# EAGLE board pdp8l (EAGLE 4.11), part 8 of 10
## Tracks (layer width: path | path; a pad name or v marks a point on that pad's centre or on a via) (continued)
N$184  (via drill 0.61) (continued)
  Route2 0.203: v4.88,181.1 4.88,182.32 6.1,183.54 6.1,195.33 8.13,197.36 8.13,198.17 37.8,227.84 37.8,231.9 45.52,239.62 47.55,239.62 48.77,240.84 A33.M1
  Route15 0.203: v20.32,131.52 16.26,135.59 16.26,137.62 15.44,138.43 15.44,144.53 14.22,145.75 14.22,147.37 13.01,148.59 13.01,160.38 9.35,164.03 9.35,168.91 8.94,169.32 8.94,170.94 8.13,171.75 8.13,172.57 6.5,174.19 6.5,179.48 v4.88,181.1
N$185  (via drill 0.61)
  Top 0.203: v24.79,150.22 24.79,144.93 25.2,144.53 25.2,125.83 23.98,124.61 C35.E1 | 47.95,189.23 v47.95,173.38 | 47.95,189.23 48.77,190.04 B33.E1 | v47.95,214.83 47.95,189.23
  Route2 0.203: v47.95,173.38 v24.79,150.22
  Route15 0.203: v47.95,214.83 34.54,228.24 34.54,238.81 33.33,240.03 33.33,243.69 A34.L1
N$186  (via drill 0.61)
  Top 0.203: v35.36,118.52 35.36,82.35 28.85,75.84 28.85,36.83 30.07,35.61 D34.M2
  Route2 0.203: v4.06,182.32 3.25,183.13 3.25,193.29 6.1,196.14 6.1,203.05 12.19,209.14 12.19,217.68 12.6,218.08 12.6,220.12 16.66,224.18 17.48,224.18 39.01,245.72 40.64,245.72 42.27,247.34 A33.K2
  Route15 0.203: v54.86,128.68 47.95,135.59 47.95,137.21 47.55,137.62 47.55,139.24 13.01,173.79 13.01,177.85 5.28,185.57 4.06,185.57 2.44,183.95 v4.06,182.32
  Bottom 0.203: v35.36,118.52 36.58,119.74 38.61,119.74 39.01,119.33 41.86,119.33 50.8,128.27 54.46,128.27 v54.86,128.68
N$187  (via drill 0.61)
  Top 0.203: v22.35,155.09 22.35,119.33 23.57,118.11 C35.H1 | v38.2,238.81 38.2,216.46 37.8,216.05 37.8,206.7 v37.39,206.3 | v46.74,205.89 47.55,205.08 47.55,186.38 v47.14,185.98
  Route2 0.203: v22.35,155.09 22.76,155.09 34.54,166.88 34.54,167.69 43.48,176.63 43.89,176.63 44.3,177.04 44.3,181.1 45.52,182.32 47.55,182.32 48.77,183.54 B33.H1
  Bottom 0.203: v38.2,238.81 34.54,238.81 34.14,238.4 A34.N1 | v37.39,206.3 37.8,205.89 v46.74,205.89 | v47.14,185.98 48.36,184.76 48.77,184.76 B33.H1
N$188  (via drill 0.61)
  Top 0.203: v36.98,122.17 37.8,122.99 37.8,137.21 37.39,137.62 37.39,151.44 37.8,151.84 37.8,168.91 v37.39,169.32 | v45.92,177.85 45.92,180.29 B33.J1 | v35.76,230.68 35.36,230.28 35.36,194.92 v36.98,193.29
  Route2 0.203: v45.92,177.85 v37.39,169.32 | v35.76,230.68 35.36,230.28 34.14,231.5 A34.R1
  Route15 0.203: v36.98,193.29 36.98,192.07 44.3,184.76 44.3,182.73 45.52,181.51 B33.J1
  Bottom 0.203: v36.98,122.17 30.89,116.08 22.35,116.08 21.13,114.86 C35.J1
N$189  (via drill 0.61)
  Top 0.203: v45.11,136.4 46.33,137.62 46.33,147.37 47.95,149 47.95,159.56 47.14,160.38 47.14,161.19 47.55,161.59 47.55,171.75 | 47.55,171.75 47.55,172.57 46.74,173.38 46.74,174.19 B33.L1 | v48.77,220.12 50.39,218.49 50.39,174.6 47.55,171.75
  Route2 0.203: v45.11,136.4 29.26,120.55 29.26,118.92 20.73,110.39 20.73,108.76 C35.L1
  Bottom 0.203: v48.77,220.12 48.36,220.52 35.36,220.52 34.14,219.3 A34.V1
N$190  (via drill 0.61)
  Top 0.203: v47.95,160.78 47.95,170.13 48.77,170.94 B33.M1 | v26.42,203.45 26.42,214.83 28.45,216.86 28.45,219.71 28.04,220.12 28.04,220.93 28.45,221.34 28.45,241.66 29.67,242.88 29.67,245.31 28.85,246.13 28.85,258.32 30.07,259.54 A34.E2
  Route2 0.203: v15.44,125.83 15.44,126.24 18.69,129.49 18.69,133.55 23.16,138.02 24.79,138.02 31.7,144.93 32.11,144.93 v47.95,160.78
  Route15 0.203: v15.44,125.83 16.26,125.02 16.26,122.99 22.35,116.89 22.35,110.39 23.57,109.17 23.57,105.51 C35.M1 | v26.42,203.45 23.57,200.61 27.23,196.95 27.23,196.14 28.85,194.51 28.85,189.64 45.11,173.38 46.74,173.38 48.77,171.35 B33.M1
N$191  (via drill 0.61)
  Top 0.203: v16.66,96.98 16.26,97.38 v16.26,121.77 | v49.17,160.78 49.17,164.44 B33.P1 | v24.79,255.47 21.95,255.47 21.95,218.49 21.13,217.68 v21.13,202.23
  Route2 0.203: v16.26,121.77 16.26,126.24 21.13,131.12 21.13,131.93 28.45,139.24 28.45,140.06 v49.17,160.78
  Route15 0.203: v24.79,255.47 25.6,254.66 29.67,254.66 A34.H2 | v21.13,202.23 26.82,196.54 26.82,195.73 28.45,194.11 28.45,188.82 39.01,178.26 39.01,177.44 47.55,168.91 47.55,166.88 48.77,165.66 B33.P1
  Bottom 0.203: v16.66,96.98 21.95,96.98 23.16,98.2 C35.P1
N$192  (via drill 0.61)
  Route2 0.203: C35.S1 23.16,91.69 19.1,91.69 18.29,90.88 9.75,90.88 1.22,99.42 2.85,101.04 2.85,105.92 8.53,111.61 8.53,112.83 18.69,122.99 18.69,127.86 32.92,142.09 34.54,142.09 47.55,155.09 47.55,156.31 49.17,157.94 B33.S1 | v14.22,228.24 30.07,244.09 30.07,246.94 A34.K2
  Route15 0.203: v14.22,228.24 14.22,227.43 15.44,226.21 15.44,201.02 25.2,191.26 25.2,187.2 32.92,179.48 32.92,178.26 49.99,161.19 49.99,158.75 B33.S1
N$193  (via drill 0.61)
  Top 0.203: v15.04,146.15 15.44,145.75 15.44,128.27 14.63,127.46 C35.D2 | 35.36,181.1 v35.36,166.88 | 35.36,181.1 38.2,183.95 38.2,191.67 39.42,192.89 B33.D2 | 35.36,181.1 35.36,189.23 34.95,189.64 34.95,245.72 32.92,245.72 32.11,244.91 32.11,243.69 30.48,242.06 A34.M2
  Route2 0.203: v15.04,146.15 15.04,146.56 v35.36,166.88
N$194  (via drill 0.61)
  Top 0.203: v20.73,144.12 19.1,142.49 19.1,126.24 17.48,124.61 C35.E2 | v44.7,145.75 44.7,188.82 43.48,190.04 B33.E2 | v31.29,191.67 31.29,233.53 30.48,234.34 A34.P2
  Bottom 0.203: v20.73,144.12 22.76,146.15 44.3,146.15 v44.7,145.75 | v31.29,191.67 39.01,191.67 39.83,190.86 42.27,190.86 B33.E2
N$195  (via drill 0.61)
  Top 0.203: v44.7,125.83 44.3,126.24 44.3,144.93 43.89,145.34 43.89,151.44 44.3,151.84 44.3,182.32 43.08,183.54 B33.H2 | v32.11,228.24 31.7,227.84 31.7,192.48 33.33,190.86 v33.33,189.23
  Route2 0.203: v32.11,228.24 30.89,228.24 A34.S2
  Bottom 0.203: v44.7,125.83 36.58,125.83 30.07,119.33 19.1,119.33 17.88,118.11 C35.H2 | v33.33,189.23 33.73,188.82 40.23,188.82 42.67,186.38 42.67,184.76 B33.H2
N$196  (via drill 0.61)
  Top 0.203: v38.2,177.85 v38.2,138.02 | v32.11,179.07 32.11,181.91 34.54,184.35 34.54,188.01 34.14,188.42 34.14,190.86 32.11,192.89 32.11,226.21 32.92,227.03 32.92,229.06 31.7,230.28 31.7,236.37 29.67,236.37 28.85,235.56 28.85,224.18 30.07,222.96 A34.U2
  Route2 0.203: v38.2,138.02 35.76,138.02 21.95,124.21 21.95,120.14 19.91,118.11 19.91,115.67 17.88,113.64 17.88,111.61 C35.K2
  Bottom 0.203: B33.K2 42.27,177.85 v38.2,177.85 38.2,178.26 37.39,179.07 v32.11,179.07
N$197  (via drill 0.61)
  Top 0.203: v230.84,253.44 228.4,251 228.4,240.03 219.46,231.09 219.46,207.52 217.42,205.49 217.42,201.83 216.21,200.61 216.21,199.39 v217.42,198.17 | v224.33,177.85 225.15,177.04 225.15,172.97 224.74,172.57 224.74,169.32 225.55,168.5 225.55,78.69 v232.87,71.37
  Route15 0.203: v217.42,198.17 217.42,195.73 218.64,194.51 218.64,183.54 v224.33,177.85 | v232.87,71.37 242.21,62.03 246.69,62.03 v271.88,36.83
  Bottom 0.203: v230.84,253.44 233.27,255.88 249.94,255.88 252.37,258.32 283.67,258.32 283.67,254.66 A14.H2 | v271.88,36.83 298.7,36.83 299.52,37.64 D13.L1
N$198  (via drill 0.61)
  Top 0.203: v18.29,102.67 18.29,99.42 17.88,99.01 C35.P2 | v35.76,163.63 34.54,162.41 34.54,132.33 32.11,129.9 v32.11,105.92
  Bottom 0.203: v18.29,102.67 18.69,103.07 32.11,103.07 | 32.11,103.07 114.61,103.07 115.42,102.26 C27.N2 | v35.76,163.63 36.98,163.63 37.39,164.03 41.45,164.03 42.27,164.85 B33.P2 | 32.11,103.07 v32.11,105.92
N$199  (via drill 0.61)
  Top 0.203: v29.67,93.73 32.11,96.16 32.11,104.7 34.54,107.14 34.54,131.52 35.36,132.33 35.36,156.72 v35.76,157.12
  Bottom 0.203: v29.67,93.73 19.1,93.73 17.88,92.51 C35.S2 | v35.76,157.12 36.17,157.53 39.01,157.53 39.83,158.34 42.27,158.34 B33.S2
N$200
  Bottom 0.203: C32.J2 52.83,113.64 54.05,112.42 60.55,112.42 61.37,111.61 C32.K1
N$201
  Top 0.203: D17.A1 251.97,66.09 249.94,64.06 249.94,63.65 D17.B1 249.94,63.25 251.97,61.21 251.97,60.81 D17.C1 251.97,60 251.97,59.59 249.94,57.56 D17.D1 249.12,56.34 249.12,51.46 D17.F1 | D17.J1 249.94,44.55 251.97,46.58 251.97,46.99 D17.H1
  Bottom 0.203: D17.J1 249.53,43.74 251.56,41.71 251.97,41.71 D17.K1 | 250.34,49.43 251.56,48.21 251.97,48.21 D17.H1 | 250.34,49.43 249.53,50.24 D17.F1 | 250.34,49.43 260.1,49.43 261.31,50.65 D16.F1
N$202  (via drill 0.61)
  Top 0.203: v85.34,145.75 85.75,146.15 85.75,181.91 86.16,182.32 86.16,185.98 87.38,187.2 87.38,188.42 86.16,189.64 86.16,219.3 v86.56,219.71
  Route2 0.203: v85.34,145.75 76.81,137.21 76.81,135.18 40.64,99.01 36.98,99.01 C34.P1
  Route15 0.203: v86.56,219.71 86.56,220.93 82.91,224.59 82.91,229.46 78.84,233.53 78.03,233.53 69.09,242.47 67.46,242.47 65.84,244.09 AB31.AL2
N$203  (via drill 0.61)
  Top 0.203: v281.23,97.79 279.6,99.42 279.6,130.71 277.98,132.33 277.98,135.99 C15.A1
  Route15 0.203: v281.23,97.79 293.42,85.6 293.42,83.16 C13.V2
N$204  (via drill 0.61)
  Top 0.203: v271.07,64.06 272.69,65.68 272.69,86.41 271.88,87.22 271.88,90.47 272.69,91.29 272.69,109.58 | 272.69,109.58 271.88,110.39 C15.K2 | v270.26,134.37 272.69,131.93 272.69,109.58
  Route2 0.203: v271.07,64.06 258.47,51.46 256.03,51.46 D16.F2
  Bottom 0.203: v270.26,134.37 273.1,134.37 273.91,133.55 C15.B1
N$205  (via drill 0.61)
  Top 0.203: v281.63,111.61 282.45,110.79 282.45,83.97 282.85,83.57 282.85,49.02 283.67,48.21 D14.H2
  Route2 0.203: v281.63,111.61 277.98,115.27 279.2,116.48 279.2,128.27 277.98,129.49 C15.C1
N$206  (via drill 0.61)
  Top 0.203: v273.51,55.93 273.51,45.77 274.32,44.96 D15.J1 | v254.41,97.38 254.41,59.18 255.63,57.96 D16.D2
  Bottom 0.203: v273.51,55.93 272.29,55.93 269.85,58.37 256.85,58.37 256.03,57.56 D16.D2 | v254.41,97.38 254,96.98 247.9,96.98 246.69,98.2 C17.P2
N$207  (via drill 0.61)
  Top 0.203: v263.75,120.14 263.75,94.94 257.25,88.44 257.25,32.36 256.03,32.36 D16.N2
  Bottom 0.203: v263.75,120.14 267.82,120.14 C15.F2
N$208
  Top 0.203: D14.N2 281.63,31.95 285.29,31.95 285.29,35.61 286.11,36.42 286.11,40.49 290.17,44.55 290.17,46.99 D14.H1
N$209
  Top 0.203: D14.M2 284.48,35.61 285.7,36.83 285.7,40.89 289.36,44.55 289.36,52.68 290.17,53.49 D14.E1
N$210  (via drill 0.61)
  Top 0.203: v285.29,49.02 286.92,47.4 286.92,46.18 | 286.92,46.18 286.92,44.96 D14.J1 | 286.92,46.18 282.45,46.18 278.38,50.24 278.38,51.05 279.2,51.87 279.2,54.71 276.35,57.56 276.35,112.42 275.13,113.64 C15.J1 | v269.44,36.83 270.26,37.64 270.26,46.18 271.07,46.99 D15.H2
  Route2 0.203: D17.N1 249.94,31.95 249.94,32.36 251.97,34.39 D17.M1
  Bottom 0.203: v285.29,49.02 272.69,49.02 271.88,48.21 D15.H2 | v269.44,36.83 254.81,36.83 253.19,35.2 D17.M1
N$211
  Route2 0.203: D15.L2 269.04,38.46 270.66,38.46 275.95,43.74 275.95,45.36 277.57,46.99 D15.H1
N$212
  Top 0.203: D15.T2 268.63,19.76 270.26,21.39 270.26,31.55 276.35,37.64 276.35,52.68 277.17,53.49 D15.E1
N$213  (via drill 0.61)
  Top 0.203: v269.04,109.58 269.44,109.17 269.44,86.41 267,83.97 267,22.2 263.35,18.54 263.35,17.73 261.31,17.73 260.5,18.54 260.5,23.42 261.72,24.64 D16.R1
  Bottom 0.203: v269.04,109.58 269.44,109.98 276.35,109.98 277.17,110.79 C15.K1
N$214  (via drill 0.61)
  Top 0.203: v120.29,146.96 120.29,156.72 119.08,157.94 B27.S2 | v178,146.56 178,154.28 178.82,155.09 B22.T2
  Bottom 0.203: v120.29,146.96 131.67,146.96 133.3,145.34 166.62,145.34 167.84,146.56 v178,146.56
N$215  (via drill 0.61)
  Top 0.203: v269.44,52.68 269.85,53.09 269.85,110.79 267,113.64 267,125.02 268.22,126.24 C15.D2
  Bottom 0.203: v269.44,52.68 285.7,52.68 286.92,51.46 D14.F1
N$216  (via drill 0.61)
  Route2 0.203: v153.62,184.76 147.93,179.07 143.46,179.07 127.61,163.22 121.51,163.22 120.29,162 116.64,162 B27.R2
  Route15 0.203: v153.62,184.76 153.62,184.35 179.63,158.34 182.07,158.34 B22.S2
N$217  (via drill 0.61)
  Route2 0.203: v89.41,157.53 89.41,157.94 97.13,165.66 97.13,166.47 114.2,183.54 114.2,185.57 115.42,186.79 B27.F2
  Bottom 0.203: v89.41,157.53 39.83,157.53 38.61,156.31 35.36,156.31 34.95,156.72 19.91,156.72 19.51,156.31 17.88,156.31 17.48,156.72 6.91,156.72 5.28,158.34 B36.S2
N$218  (via drill 0.61)
  Top 0.203: v50.39,146.96 50.8,147.37 50.8,205.08 51.61,205.89 v51.61,213.21 | v106.48,215.65 106.48,221.74 A28A.U2
  Bottom 0.203: v50.39,146.96 3.66,146.96 2.03,148.59 B36.V2 | v51.61,213.21 54.05,215.65 v106.48,215.65 | A27.T2 115.42,224.99 114.2,223.77 108.1,223.77 106.88,222.56 A28A.U2
N$219
  Bottom 0.203: B28.J2 103.63,180.29 105.66,178.26 B28.K2 106.88,178.26 108.1,179.48 117.45,179.48 | 117.45,179.48 116.64,180.29 116.23,180.29 B27.J2 | 117.45,179.48 118.67,178.26 B27.K2
N$220  (via drill 0.61)
  Top 0.203: v101.6,175.41 104.44,178.26 104.44,207.52 101.6,210.36 v101.6,211.18
  Route2 0.203: v101.6,175.41 95.1,168.91 95.1,164.44 85.75,155.09 85.75,154.28 80.06,148.59 80.06,147.78 71.12,138.84 71.12,136.8 70.31,135.99 70.31,134.77 67.87,132.33 67.87,131.93 33.73,97.79 33.73,95.76 C34.R1
  Route15 0.203: v101.6,211.18 101.6,211.58 71.53,241.66 v71.12,241.66
  Bottom 0.203: v71.12,241.66 68.68,241.66 AB31.AM2
N$221  (via drill 0.61)
  Top 0.203: D25.L2 141.43,38.86 142.65,40.08 142.65,54.71 142.24,55.12 142.24,55.93 142.65,56.34 142.65,70.16 140.21,72.59 140.21,79.5 142.65,81.94 142.65,105.92 141.43,107.14 C25.L2 | v121.92,255.47 120.7,254.25 120.7,175.82 121.11,175.41 121.11,134.37 117.86,131.12 117.86,120.55 120.29,118.11 120.29,110.39 119.48,109.58 v119.48,108.76
  Bottom 0.203: v121.92,255.47 126.8,255.47 128.02,256.69 A26.F2 | v119.48,108.76 119.89,109.17 138.18,109.17 138.99,108.36 140.61,108.36 C25.L2
N$222  (via drill 0.61)
  Top 0.203: v252.37,70.97 251.16,72.19 251.16,85.19 246.69,85.19 C17.U2
  Route15 0.203: v252.37,70.97 264.16,59.18 269.04,59.18 280.01,48.21 281.63,48.21 299.52,30.33 301.55,30.33 302.77,29.11 D13.P1
N$223  (via drill 0.61)
  Top 0.203: v293.42,79.5 292.2,78.28 292.2,69.34 298.3,63.25 298.3,50.65 301.55,47.4 301.55,33.58 300.33,32.36 D13.N1
  Route15 0.203: v293.42,79.5 293.42,80.72 292.2,81.94 292.2,86 281.63,96.57 277.57,96.57 276.35,97.79 276.35,99.82 275.13,101.04 C15.N1
N$224  (via drill 0.61)
  Top 0.203: 151.99,103.48 151.99,36.42 151.18,35.61 D25.M1 | 151.99,103.48 151.18,104.29 C25.M1 | v150.77,155.91 151.99,154.69 151.99,103.48
  Route15 0.203: v150.77,155.91 136.55,170.13 136.55,175.82 128.83,183.54 128.83,186.79 B26.F2
N$225  (via drill 0.61)
  Top 0.203: v153.62,55.12 155.65,57.15 155.65,107.54 158.5,110.39 v158.5,120.14 158.5,120.55 155.65,123.39 155.65,163.63 152.81,166.47 152.81,169.32 155.25,171.75 155.25,189.64 152.81,189.64 152.4,189.23 152.4,188.42 v150.37,188.42
  Route2 0.203: v153.62,55.12 152.81,54.3 151.59,54.3 D25.E1
  Bottom 0.203: v158.5,120.14 154.84,123.8 151.59,123.8 C25.E1 | v150.37,188.42 149.96,188.82 143.05,188.82 141.83,187.6 B25.F2
N$226  (via drill 0.61)
  Top 0.203: v130.05,259.94 130.45,260.35 130.45,261.16 130.86,261.57 133.3,261.57 133.3,88.85 v135.33,86.82 | D25.U2 144.68,16.51 145.9,17.73 145.9,69.75 148.74,72.59 148.74,79.5 145.09,83.16 145.09,85.19 C25.U2
  Bottom 0.203: v130.05,259.94 130.86,259.13 138.99,259.13 140.61,257.5 A25.F2 | v135.33,86.82 135.74,87.22 142.65,87.22 143.87,86 C25.U2
N$227  (via drill 0.61)
  Route2 0.203: v210.51,229.06 241,259.54 241,261.16 242.62,262.79 A17.D2
  Bottom 0.203: v210.51,229.06 208.89,227.43 196.7,227.43 195.88,228.24 A21.S2
N$228  (via drill 0.61)
  Top 0.203: v190.6,257.91 190.6,227.43 191.82,226.21 A21.T2
  Bottom 0.203: v190.6,257.91 191.82,259.13 244.65,259.13 245.47,259.94 A17.E2
N$229
  Bottom 0.203: A21.C2 195.88,266.85 197.1,268.07 204.42,268.07 210.11,262.38 228.8,262.38 229.62,263.2 A18.D2
N$230
  Bottom 0.203: A21.D2 192.63,263.2 194.26,261.57 229.21,261.57 230.02,260.76 232.87,260.76 A18.E2
N$231  (via drill 0.61)
  Top 0.203: v197.1,243.28 197.1,257.91 195.48,259.54 A21.E2
  Bottom 0.203: v197.1,243.28 197.51,242.88 234.9,242.88 236.12,244.09 A18.L1
N$232  (via drill 0.61)
  Route15 0.203: v227.99,255.47 227.99,255.07 237.74,245.31 237.74,243.69 239.37,242.06 A18.M1
  Bottom 0.203: v227.99,255.47 225.15,258.32 193.45,258.32 192.63,257.5 A21.F2
N$233  (via drill 0.61)
  Top 0.203: v215.8,255.07 216.21,255.47 216.21,261.57 217.42,262.79 A19.D2
  Bottom 0.203: v215.8,255.07 215.39,255.47 197.1,255.47 195.88,254.25 A21.H2
N$234
  Top 0.203: A21.J2 192.63,251.41 193.85,252.63 193.85,261.16 200.76,268.07 225.15,268.07 225.15,262.79 223.11,260.76 221.08,260.76 A19.E2
N$235  (via drill 0.61)
  Top 0.203: v218.24,246.13 223.11,246.13 223.11,244.91 A19.L1
  Bottom 0.203: v218.24,246.13 197.1,246.13 195.88,247.34 A21.K2
N$236  (via drill 0.61)
  Top 0.203: v192.63,240.44 192.63,243.28 192.23,243.69 A21.L2
  Bottom 0.203: v192.63,240.44 193.04,240.03 225.55,240.03 226.37,240.84 A19.M1
N$237
  Top 0.203: A21.M2 195.88,241.66 200.35,241.66 200.35,257.1 204.42,261.16 204.42,262.79 A20.D2
N$238
  Top 0.203: A21.N2 192.63,238.4 197.1,238.4 197.1,238.81 198.32,240.03 203.61,240.03 203.61,254.25 207.67,258.32 207.67,259.54 A20.E2
N$239
  Top 0.203: A21.P2 195.88,235.15 200.35,235.15 200.35,235.97 208.48,244.09 210.51,244.09 A20.L1
N$240
  Top 0.203: A21.R2 192.63,231.5 197.1,231.5 197.1,231.09 197.92,230.28 212.95,230.28 212.95,240.03 213.77,240.84 A20.M1
N$241  (via drill 0.61)
  Top 0.203: v229.62,195.73 229.62,194.11 B18.D2
  Bottom 0.203: v229.62,195.73 229.21,195.33 197.1,195.33 195.88,196.54 B21.C2
N$242  (via drill 0.61)
  Route15 0.203: v192.23,191.67 192.23,192.89 B21.D2
  Bottom 0.203: v192.23,191.67 192.23,189.23 232.05,189.23 232.87,190.04 B18.E2
N$243  (via drill 0.61)
  Top 0.203: v197.1,178.66 193.85,181.91 193.85,189.23 194.67,190.04 B21.E2
  Bottom 0.203: v197.1,178.66 199.14,176.63 229.21,176.63 230.02,175.82 235.31,175.82 236.12,175.01 B18.L1
N$244  (via drill 0.61)
  Top 0.203: v238.56,189.23 238.56,175.82 239.37,175.01 239.37,172.16 B18.M1
  Bottom 0.203: v238.56,189.23 238.15,188.82 193.85,188.82 192.63,187.6 B21.F2
N$245  (via drill 0.61)
  Top 0.203: v197.1,190.86 197.1,186.38 195.48,184.76 B21.H2 | v216.61,191.67 217.42,192.48 217.42,192.89 B19.D2
  Bottom 0.203: v197.1,190.86 197.92,191.67 v216.61,191.67
N$246  (via drill 0.61)
  Route2 0.203: v217.02,184.76 218.64,186.38 218.64,188.42 220.27,190.04 B19.E2
  Bottom 0.203: v217.02,184.76 214.99,182.73 193.85,182.73 192.63,181.51 B21.J2
N$247
  Bottom 0.203: B21.K2 195.88,177.44 197.1,176.22 221.89,176.22 223.11,175.01 B19.L1
N$248  (via drill 0.61)
  Top 0.203: v227.58,174.19 227.18,173.79 227.18,172.16 B19.M1
  Bottom 0.203: v227.58,174.19 226.77,173.38 223.11,173.38 220.68,175.82 193.45,175.82 192.63,175.01 B21.L2
N$249  (via drill 0.61)
  Top 0.203: v200.35,193.29 200.35,180.7 197.1,177.44 197.1,173.79 195.48,172.16 B21.M2
  Bottom 0.203: v200.35,193.29 204.01,193.29 B20.D2
N$250
  Route2 0.203: B21.N2 192.23,168.91 192.23,172.57 206.04,186.38 206.04,188.82 207.26,190.04 B20.E2
N$251  (via drill 0.61)
  Top 0.203: v199.95,173.79 199.95,165.25 195.88,165.25 B21.P2
  Bottom 0.203: v199.95,173.79 200.35,173.38 209.7,173.38 210.51,174.19 B20.L1
N$252  (via drill 0.61)
  Top 0.203: v213.77,166.88 213.77,170.94 B20.M1
  Bottom 0.203: v213.77,166.88 210.51,163.63 193.85,163.63 192.63,162.41 B21.R2
N$253
  Route2 0.203: A26.P2 132.49,235.15 136.14,235.15 153.21,252.22 154.84,252.22 156.46,253.85 A24.H2
N$254  (via drill 0.61)
  Top 0.203: v120.29,175.01 120.29,204.27 118.67,205.89 118.67,219.71 104.85,233.53 v104.85,237.59
  Route2 0.203: v120.29,175.01 96.32,151.03 94.28,151.03 81.28,138.02 80.47,138.02 36.98,94.54 36.98,92.51 C34.S1
  Bottom 0.203: v104.85,237.59 104.85,239.62 67.06,239.62 65.84,238.4 AB31.AN2
N$255  (via drill 0.61)
  Top 0.203: v99.97,106.32 101.6,107.95 101.6,165.66 v100.38,166.88
  Route15 0.203: v77.22,172.97 72.75,177.44 72.75,177.85 70.31,180.29 70.31,181.91 68.68,183.54 AB31.BH2
  Bottom 0.203: v99.97,106.32 99.57,106.32 96.72,103.48 37.8,103.48 36.98,104.29 C34.M1 | v100.38,166.88 94.28,172.97 v77.22,172.97
N$256  (via drill 0.61)
  Top 0.203: v66.65,207.52 66.24,207.92 66.24,224.18 65.43,224.99 AB31.AT2
  Route2 0.203: v86.56,187.6 63.4,164.44 63.4,158.34 62.18,157.12 62.18,154.69 54.05,146.56 54.05,145.75 50.39,142.09 50.39,135.59 39.01,124.21 36.98,124.21 C34.E1
  Route15 0.203: v66.65,207.52 v86.56,187.6
N$257  (via drill 0.61)
  Top 0.203: v65.43,203.05 65.43,218.49 AB31.AV2
  Route2 0.203: v20.32,153.87 18.69,155.5 19.51,156.31 19.51,157.12 v65.43,203.05
  Route15 0.203: v20.32,153.87 20.73,153.47 20.73,151.44 23.57,148.59 23.57,143.71 26.82,140.46 26.82,139.24 28.45,137.62 28.45,135.59 31.7,132.33 31.7,131.52 32.92,130.3 32.92,127.46 C34.D1
N$258  (via drill 0.61)
  Top 0.203: v40.23,143.71 40.23,138.84 38.2,136.8 38.2,87.63 36.98,86.41 C34.U1 | v67.87,143.31 67.87,151.84 AB31.BU2
  Bottom 0.203: v40.23,143.71 67.46,143.71 v67.87,143.31
N$259
  Route15 0.203: A16.E1 265.79,259.94 267.41,259.94 275.95,251.41 275.95,249.38 277.17,248.16 A15.K1
N$260
  Top 0.203: A15.L1 273.91,244.91 273.51,245.31 273.51,248.56 272.69,249.38 272.69,277.01 275.95,280.26 275.95,281.08 275.13,281.89 265.38,281.89 265.38,273.76 A16.A1
N$261
  Top 0.203: A16.U2 258.88,222.96 260.1,224.18 260.1,238.81 260.5,239.22 260.5,255.88 261.31,256.69 A16.F1
N$262
  Top 0.203: A16.V2 256.03,219.71 256.44,220.12 256.44,224.59 256.85,224.99 256.85,229.46 257.25,229.87 257.25,263.2 261.72,267.67 261.72,269.29 A16.B1
N$263
  Top 0.203: A16.C1 265.79,266.45 269.44,266.45 269.44,220.52 268.63,219.71 A15.V2
N$264  (via drill 0.61)
  Top 0.203: v266.19,223.37 266.6,223.77 266.6,248.16 265.79,248.97 265.79,253.03 265.38,253.44 A16.H1
  Bottom 0.203: v266.19,223.37 267,222.56 270.66,222.56 A15.U2
N$265
  Route15 0.203: B17.E1 253.19,190.45 254.41,190.45 263.35,181.51 263.35,179.48 264.57,178.26 B16.K1
N$266
  Top 0.203: B17.U2 246.28,153.06 247.9,154.69 247.9,177.44 250.75,180.29 250.75,182.73 249.53,183.95 249.53,186.79 B17.F1
N$267
  Route15 0.203: A22.T2 179.22,226.21 179.22,227.84 161.34,245.72 159.31,245.72 157.68,247.34 A24.K2
N$268
  Route15 0.203: A24.J2 154.43,250.19 158.9,250.19 178.82,230.28 180.85,230.28 182.07,229.06 A22.S2
N$269  (via drill 0.61)
  Top 0.203: v175.56,173.79 175.97,173.38 175.97,172.16 B23.M1
  Bottom 0.203: v175.56,173.79 175.16,173.38 144.68,173.38 144.68,177.04 B25.K2
N$270
  Route2 0.203: A25.N2 141.83,238.4 144.68,238.4 148.34,242.06 149.56,242.06 162.97,255.47 165,255.47 166.22,256.69 A23.F2
N$271
  Route2 0.203: A26.N2 129.24,238.4 132.49,238.4 138.18,244.09 138.99,244.09 150.37,255.47 151.59,255.47 153.21,257.1 A24.F2
N$272  (via drill 0.61)
  Top 0.203: v156.06,259.13 156.06,257.1 146.3,247.34 146.3,243.69 144.68,242.06 A25.M2
  Bottom 0.203: v156.06,259.13 156.46,258.72 174.35,258.72 175.56,259.94 A23.E1
N$273  (via drill 0.61)
  Top 0.203: v142.24,235.97 142.65,236.37 142.65,242.47 141.43,243.69 A25.L2
  Bottom 0.203: v142.24,235.97 142.65,236.37 167.84,236.37 169.06,235.15 A23.P2
N$274  (via drill 0.61)
  Route15 0.203: v148.74,241.25 144.68,245.31 144.68,246.94 A25.K2
  Bottom 0.203: v148.74,241.25 149.96,240.03 174.75,240.03 175.56,240.84 A23.M1
N$275
  Route2 0.203: A25.P2 145.09,235.15 148.74,235.15 149.96,236.37 154.43,236.37 167.84,249.78 167.84,251.82 169.47,253.44 A23.H2
N$276  (via drill 0.61)
  Top 0.203: v142.24,255.88 139.8,253.44 139.8,233.53 141.02,232.31 A25.R2
  Bottom 0.203: v142.24,255.88 144.68,258.32 171.5,258.32 172.31,257.5 A23.F1
N$277  (via drill 0.61)
  Top 0.203: v143.46,237.59 143.05,237.19 143.05,227.84 141.43,226.21 A25.T2
  Bottom 0.203: v143.46,237.59 145.49,239.62 171.09,239.62 172.31,238.4 A23.N1
N$278
  Bottom 0.203: A25.S2 145.09,229.06 146.3,230.28 162.56,230.28 163.37,231.09 166.22,231.09 A23.R2
N$279
  Route2 0.203: A23.K2 170.28,248.16 170.28,252.22 177.6,259.54 177.6,261.16 179.22,262.79 A22.D2
N$280
  Route2 0.203: A23.J2 167.03,251.41 167.03,251.82 167.44,252.22 167.44,253.44 178.82,264.82 180.85,264.82 182.07,266.04 A22.C2
N$281
  Top 0.203: A23.H1 176.38,254.66 177.6,255.88 177.6,257.5 180.03,259.94 182.07,259.94 A22.E2
N$282
  Top 0.203: A23.J1 173.53,251.41 178,251.41 178,255.88 178.82,256.69 A22.F2
N$283
  Route2 0.203: A23.S2 170.28,229.06 170.28,233.12 171.09,233.93 171.09,239.62 178,246.53 178,247.34 180.85,250.19 180.85,252.22 182.07,253.44 A22.H2
N$284
  Route2 0.203: A23.T2 167.03,226.21 167.03,230.28 167.84,231.09 167.84,237.19 177.6,246.94 177.6,248.56 179.22,250.19 A22.J2
N$285
  Top 0.203: A23.R1 173.13,231.09 174.75,229.46 174.75,227.84 175.16,227.43 177.6,227.43 177.6,235.97 178,236.37 178,242.47 179.22,243.69 A22.L2
N$286  (via drill 0.61)
  Top 0.203: v177.6,249.78 177.6,236.78 176.38,235.56 A23.P1
  Bottom 0.203: v177.6,249.78 179.22,248.16 182.07,248.16 A22.K2
N$287  (via drill 0.61)
  Top 0.203: v141.43,170.13 141.43,174.19 B25.L2
  Bottom 0.203: v141.43,170.13 141.83,169.72 167.44,169.72 167.84,169.32 167.84,166.88 165,166.88 164.59,166.47 162.97,166.47 162.15,165.66 162.15,163.63 167.84,163.63 169.06,164.85 B23.P2
N$288  (via drill 0.61)
  Route2 0.203: v161.75,186.38 147.12,171.75 145.09,171.75 B25.M2
  Bottom 0.203: v161.75,186.38 164.59,189.23 172.31,189.23 173.13,190.04 175.56,190.04 B23.E1
N$289
  Route2 0.203: B25.N2 141.83,168.5 145.9,168.5 162.97,185.57 165,185.57 166.22,186.79 B23.F2
N$290  (via drill 0.61)
  Top 0.203: v146.3,177.44 146.3,167.28 144.68,165.66 B25.P2
  Bottom 0.203: v146.3,177.44 151.18,182.32 153.21,182.32 156.46,185.57 165.81,185.57 167.03,184.35 169.06,184.35 B23.H2
N$291  (via drill 0.61)
  Route2 0.203: v167.03,185.57 143.87,162.41 141.83,162.41 B25.R2
  Bottom 0.203: v167.03,185.57 168.66,187.2 172.31,187.2 B23.F1
N$292
  Bottom 0.203: B25.S2 145.09,159.16 146.3,160.38 162.97,160.38 164.19,161.59 166.22,161.59 B23.R2
N$293  (via drill 0.61)
  Route2 0.203: v161.75,158.75 161.75,159.16 169.06,166.47 170.69,166.47 172.31,168.1 B23.N1
  Bottom 0.203: v161.75,158.75 159.72,156.72 142.65,156.72 141.83,155.91 B25.T2
N$294  (via drill 0.61)
  Top 0.203: v184.91,202.23 184.51,202.64 184.51,239.22 182.88,240.84 A22.M2
  Route2 0.203: v184.91,202.23 168.66,185.98 168.66,184.35 167.03,182.73 167.03,181.51 B23.J2
N$295  (via drill 0.61)
  Top 0.203: v168.66,233.12 168.66,179.07 169.47,178.26 B23.K2
  Bottom 0.203: v168.66,233.12 169.06,233.53 172.72,233.53 176.78,237.59 178.82,237.59 A22.N2
N$296
  Top 0.203: B23.J1 173.53,181.51 174.35,182.32 174.35,223.37 179.22,228.24 179.22,231.09 A22.R2
N$297  (via drill 0.61)
  Top 0.203: v184.91,185.98 184.1,186.79 184.1,233.12 182.88,234.34 A22.P2
  Bottom 0.203: v184.91,185.98 178.41,185.98 176.78,184.35 B23.H1
N$298  (via drill 0.61)
  Top 0.203: v184.1,155.5 183.69,155.91 183.69,195.33 182.88,196.14 B22.C2
  Bottom 0.203: v184.1,155.5 181.66,155.5 177.19,159.97 175.56,159.97 175.16,159.56 170.69,159.56 170.28,159.16 B23.S2
N$299  (via drill 0.61)
  Top 0.203: v172.72,157.12 174.75,159.16 174.75,191.26 176.78,193.29 178.82,193.29 B22.D2
  Bottom 0.203: v172.72,157.12 171.91,156.31 167.84,156.31 167.44,155.91 B23.T2
N$300  (via drill 0.61)
  Top 0.203: v178,190.04 177.6,189.64 177.6,166.47 176.78,165.66 B23.P1
  Bottom 0.203: v178,190.04 182.07,190.04 B22.E2
N$301  (via drill 0.61)
  Top 0.203: v171.91,183.95 171.91,163.22 172.72,162.41 B23.R1
  Bottom 0.203: v171.91,183.95 174.75,186.79 178.82,186.79 B22.F2
N$302
  Bottom 0.203: B26.K2 131.67,177.04 131.67,172.97 131.27,172.97 130.45,172.16 130.45,170.13 140.21,170.13 143.05,172.97 161.75,172.97 162.97,171.75 B24.M1
N$303
  Bottom 0.203: B26.L2 129.24,174.19 129.24,169.72 137.77,169.72 141.02,166.47 155.25,166.47 156.46,165.25 B24.P2
N$304
  Bottom 0.203: B26.M2 132.08,172.16 132.08,176.63 141.02,176.63 147.12,182.73 152.81,182.73 160.12,190.04 162.97,190.04 B24.E1
N$305
  Route2 0.203: B26.N2 129.24,168.5 131.67,168.5 152.81,189.64 153.62,189.64 154.43,188.82 153.62,188.01 B24.F2
N$306  (via drill 0.61)
  Top 0.203: v157.28,163.22 158.5,164.44 158.5,182.73 157.68,183.54 B24.H2
  Bottom 0.203: v157.28,163.22 156.87,163.63 141.43,163.63 138.58,166.47 133.71,166.47 132.49,165.25 B26.P2
N$307
  Route2 0.203: B26.R2 129.24,162.41 132.49,162.41 141.02,170.94 141.83,170.94 156.46,185.57 158.5,185.57 159.72,186.79 B24.F1
N$308
  Bottom 0.203: B26.S2 132.49,159.16 134.11,160.78 152.4,160.78 153.21,161.59 B24.R2
N$309  (via drill 0.61)
  Top 0.203: v158.9,158.34 158.9,166.47 160.12,167.69 B24.N1
  Bottom 0.203: v158.9,158.34 157.68,157.12 130.45,157.12 129.24,155.91 B26.T2
N$310  (via drill 0.61)
  Top 0.203: v178.41,179.48 179.22,178.66 179.22,175.41 B22.L2
  Bottom 0.203: v178.41,179.48 162.15,179.48 160.93,180.7 B24.J1
N$311
  Bottom 0.203: B24.H1 164.19,183.95 165.41,182.73 179.22,182.73 182.07,185.57 183.29,185.57 183.69,185.17 183.69,178.26 182.88,178.26 B22.K2
N$312
  Bottom 0.203: B24.K2 157.68,178.26 158.5,179.07 177.6,179.07 178,178.66 178.82,178.66 179.22,179.07 179.22,180.29 B22.J2
N$313
  Bottom 0.203: B24.J2 154.43,181.51 155.25,182.32 180.85,182.32 181.25,181.91 182.07,181.91 182.47,182.32 182.47,183.54 B22.H2
N$314
  Route2 0.203: B24.S2 157.68,159.16 160.93,159.16 168.66,166.88 169.47,166.88 172.31,169.72 180.85,169.72 182.07,170.94 B22.M2
N$315
  Route2 0.203: B24.T2 154.43,155.91 158.5,155.91 159.31,156.72 165.81,156.72 175.56,166.47 177.6,166.47 178.82,167.69 B22.N2
N$316
  Bottom 0.203: B24.P1 164.19,165.25 165.41,166.47 181.25,166.47 182.07,165.66 B22.P2
N$317
  Bottom 0.203: B24.R1 160.93,162.41 161.75,163.22 178,163.22 178.82,162.41 B22.R2
N$318  (via drill 0.61)
  Top 0.203: v24.38,194.11 24.38,195.33 25.2,196.14 25.2,203.86 24.79,204.27 24.79,207.92 25.6,208.74 25.6,245.31 23.98,246.94 A35.K1
  Bottom 0.203: v24.38,194.11 25.2,194.92 32.11,194.92 32.92,194.11 B34.D1
N$319  (via drill 0.61)
  Top 0.203: v21.54,189.23 21.95,189.64 21.95,217.68 22.35,218.08 22.35,235.56 22.76,235.97 22.76,240.44 23.16,240.84 A35.M1
  Bottom 0.203: v21.54,189.23 21.95,188.82 31.7,188.82 33.33,190.45 35.76,190.45 B34.E1
N$320  (via drill 0.61)
  Top 0.203: v39.42,229.87 41.05,228.24 41.05,218.49 38.2,215.65 38.2,194.92 37.8,194.51 37.8,185.57 36.98,184.76 B34.H1
  Bottom 0.203: v39.42,229.87 35.76,233.53 25.6,233.53 24.38,234.75 A35.P1
N$321  (via drill 0.61)
  Top 0.203: v33.73,227.03 34.54,226.21 34.54,189.23 34.95,188.82 34.95,182.73 33.73,181.51 B34.J1
  Bottom 0.203: v33.73,227.03 33.33,227.43 28.04,227.43 27.23,228.24 24.38,228.24 A35.S1
N$322  (via drill 0.61)
  Top 0.203: v22.35,175.82 22.35,217.27 23.16,218.08 23.16,221.74 A35.U1
  Bottom 0.203: v22.35,175.82 27.64,175.82 28.85,174.6 32.92,174.6 B34.L1
N$323  (via drill 0.61)
  Top 0.203: v11.38,214.02 9.75,215.65 9.75,271.32 15.04,271.32 18.69,267.67 18.69,266.04 16.26,263.6 16.26,259.54 14.63,257.91 A35.F2
  Route15 0.203: v11.38,214.02 12.19,213.21 12.19,207.52 13.01,206.7 13.01,199.39 22.35,190.04 22.35,187.6 34.54,175.41 34.54,173.79 36.17,172.16 B34.M1
N$324  (via drill 0.61)
  Route15 0.203: v3.25,249.38 3.25,218.08 0.81,215.65 0.81,203.05 12.6,191.26 12.6,186.79 32.51,166.88 34.14,166.88 35.76,165.25 B34.P1
  Bottom 0.203: v3.25,249.38 13.01,249.38 13.82,250.19 A35.J2
N$325  (via drill 0.61)
  Top 0.203: v18.29,157.12 18.69,157.53 18.69,187.6 15.85,190.45 15.85,207.11 13.82,209.14 v13.82,214.02 | v16.26,220.52 15.44,221.34 15.44,242.88 14.63,243.69 A35.L2
  Bottom 0.203: v18.29,157.12 34.54,157.12 35.76,158.34 B34.S1 | v13.82,214.02 10.16,217.68 10.16,220.52 v16.26,220.52
N$326  (via drill 0.61)
  Top 0.203: v19.51,191.67 18.69,192.48 18.69,225.4 16.26,227.84 v16.26,231.9
  Bottom 0.203: v19.51,191.67 28.85,191.67 29.67,190.86 B34.E2 | v16.26,231.9 15.04,231.9 A35.R2
N$327
  Route15 0.203: B34.D2 26.42,194.11 26.42,196.14 21.13,201.42 20.73,201.42 20.32,201.83 20.32,217.27 19.51,218.08 19.51,235.15 18.29,236.37 16.66,236.37 15.04,238 A35.N2
N$328  (via drill 0.61)
  Top 0.203: v28.85,220.52 28.85,185.57 29.67,184.76 B34.H2
  Bottom 0.203: v28.85,220.52 25.2,224.18 16.26,224.18 15.04,225.4 A35.T2
N$329  (via drill 0.61)
  Top 0.203: v21.54,183.13 19.51,185.17 19.51,190.45 16.26,193.7 16.26,207.52 14.63,209.14 14.63,218.49 A35.V2
  Bottom 0.203: v21.54,183.13 21.95,182.73 29.67,182.73 29.67,178.26 B34.K2
N$330  (via drill 0.61)
  Route15 0.203: v110.13,147.37 202.39,55.12 208.89,55.12 227.58,36.42 234.09,36.42 241.4,29.11 245.47,29.11 D17.P2 | v26.42,153.87 26.42,154.28 25.6,155.09 25.6,159.56 12.19,172.97 12.19,173.79 9.35,176.63 9.35,177.44 6.5,180.29 6.5,182.32 5.28,183.54 B36.H2
  Bottom 0.203: v110.13,147.37 70.31,147.37 66.65,151.03 58.93,151.03 56.08,153.87 v26.42,153.87
N$331  (via drill 0.61)
  Route15 0.203: v123.95,96.16 82.09,138.02 82.09,141.68 62.59,161.19 61.77,161.19 45.92,177.04 45.52,177.04 45.11,177.44 45.11,179.07 v30.48,193.7
  Bottom 0.203: v123.95,96.16 126.39,93.73 132.08,93.73 135.74,90.07 211.73,90.07 212.14,90.47 265.38,90.47 266.19,91.29 269.85,91.29 270.66,92.1 C15.S2 | v30.48,193.7 29.26,192.48 6.91,192.48 5.28,190.86 B36.E2
N$332  (via drill 0.61)
  Top 0.203: v10.57,188.82 12.6,186.79 v12.6,166.06 | v242.21,17.32 242.62,16.92 242.62,13.26 D17.V2
  Route15 0.203: v12.6,166.06 13.01,166.06 13.82,165.25 13.82,164.44 18.69,159.56 18.69,157.94 19.1,157.53 19.1,152.25 19.51,151.84 19.51,138.02 38.2,119.33 38.2,117.7 53.65,102.26 53.65,96.98 55.27,95.35 55.27,94.13 56.9,92.51 56.9,86.41 60.15,83.16 60.15,79.5 70.71,68.94 70.71,67.31 v95.91,42.11
  Bottom 0.203: v10.57,188.82 1.63,188.82 1.63,192.89 B36.D2 | v95.91,42.11 97.94,40.08 124.36,40.08 143.87,20.57 150.37,20.57 153.62,17.32 v242.21,17.32
N$333  (via drill 0.61)
  Route2 0.203: v71.12,131.52 71.53,131.52 76,135.99 76,138.43 115.82,178.26 117.45,178.26 143.87,204.67 147.52,204.67 158.09,215.24 158.9,215.24 159.31,215.65 165.41,215.65 227.99,278.23 229.21,278.23 230.43,279.45 233.27,279.45 234.49,280.67 242.21,280.67 242.62,281.08 245.47,281.08 245.87,281.48 249.94,281.48 251.56,283.11 270.26,283.11 271.48,284.33 325.93,284.33 v328.78,281.48
  Route15 0.203: v14.22,137.62 13.01,138.84 13.01,144.53 12.6,144.93 12.6,153.06 11.38,154.28 11.38,157.94 B36.S1
  Bottom 0.203: v14.22,137.62 17.07,134.77 42.67,134.77 45.52,131.93 47.95,131.93 48.36,132.33 51.21,132.33 52.02,131.52 v71.12,131.52 | v328.78,281.48 329.18,281.89 360.88,281.89 361.7,281.08 362.51,281.08 363.73,282.3 387.3,282.3 388.52,281.08 389.33,281.08 390.14,281.89 439.32,281.89 445.41,275.79 451.1,275.79 451.92,274.98 451.92,270.51 A01.B1
N$334  (via drill 0.61)
  Route2 0.203: v74.37,148.18 74.37,148.59 82.91,157.12 82.91,157.94 112.57,187.6 112.57,188.01 112.98,188.42 113.79,188.42 124.36,198.98 125.58,198.98 128.02,201.42 129.24,201.42 134.52,196.14 143.46,205.08 147.12,205.08 157.68,215.65 158.5,215.65 158.9,216.05 159.72,216.05 v172.72,229.06 | v327.96,210.36 327.96,212.39 339.75,224.18 340.97,224.18 353.16,236.37 365.35,236.37 371.86,242.88 378.76,242.88 381.61,245.72 404.77,245.72 407.62,242.88 408.43,242.88 413.31,247.75 414.12,247.75 424.69,258.32 424.69,259.13 431.6,266.04 431.6,270.51 438.91,277.83 442.57,277.83 454.36,266.04 455.17,266.85 A01.C1
  Route15 0.203: v57.71,160.78 61.77,160.78 v74.37,148.18 | v299.11,230.28 311.71,217.68 314.15,217.68 319.02,212.8 319.84,212.8 v321.46,211.18
  Bottom 0.203: v57.71,160.78 54.05,160.78 54.05,162 52.83,163.22 45.52,163.22 43.08,160.78 30.89,160.78 28.45,163.22 13.41,163.22 11.79,164.85 B36.P1 | v172.72,229.06 173.53,229.87 188.16,229.87 191.41,233.12 233.27,233.12 236.12,230.28 251.97,230.28 254.81,233.12 296.27,233.12 v299.11,230.28 | v321.46,211.18 322.27,210.36 v327.96,210.36
N$335  (via drill 0.61)
  Route15 0.203: v156.87,103.07 123.95,135.99 123.95,136.8 v93.88,166.88
  Bottom 0.203: v156.87,103.07 256.03,103.07 258.88,100.23 267,100.23 267.82,101.04 C15.N2 | v93.88,166.88 90.63,170.13 78.84,170.13 76,172.97 52.83,172.97 49.99,170.13 13.01,170.13 11.79,171.35 B36.M1
N$336  (via drill 0.61)
  Route15 0.203: v218.24,81.13 217.02,81.13 162.15,135.99 162.15,136.8 v128.42,170.54
  Bottom 0.203: v218.24,81.13 230.84,81.13 233.68,83.97 267,83.97 267.82,83.16 C15.V2 | v128.42,170.54 125.58,173.38 80.87,173.38 78.44,175.82 55.68,175.82 54.86,176.63 28.04,176.63 22.35,182.32 9.35,182.32 8.53,181.51 B36.J1
N$337
  Top 0.203: B36.E1 11.38,191.26 13.01,192.89 13.01,261.57 14.22,262.79 A35.D2
N$338  (via drill 0.61)
  Top 0.203: v16.66,268.07 12.6,264.01 12.6,208.74 9.75,205.89 9.75,195.33 8.53,194.11 B36.D1
  Bottom 0.203: v16.66,268.07 18.29,269.7 19.91,269.7 A35.B1
N$339  (via drill 0.61)
  Route15 0.203: v220.68,96.16 181.25,135.59 181.25,138.02 v158.09,161.19 | v74.37,166.88 70.31,166.88 v30.07,207.11
  Bottom 0.203: v220.68,96.16 221.08,96.57 225.15,96.57 230.84,90.88 247.09,90.88 249.53,93.32 276.35,93.32 277.17,92.51 C15.S1 | v158.09,161.19 156.06,163.22 138.58,163.22 138.18,163.63 78.03,163.63 74.78,166.88 v74.37,166.88 | v30.07,207.11 28.85,208.33 18.29,208.33 10.16,200.2 8.53,200.2 B36.B1
N$340  (via drill 0.61)
  Top 0.203: v182.88,154.28 184.51,152.65 184.51,35.61 203.61,16.51 203.61,12.04 212.14,3.5 286.92,3.5 v286.92,7.98
  Route2 0.203: v286.92,7.98 288.54,6.35 292.61,10.41 303.58,10.41 305.61,12.45 D12.V2
  Route15 0.203: v182.88,154.28 123.14,214.02 123.14,214.83 122.33,215.65 122.33,216.46 114.2,224.59 114.2,224.99 69.09,270.1 67.87,270.1 59.33,278.64 36.98,278.64 33.33,282.3 24.38,273.36 A35.A1
N$341  (via drill 0.61)
  Route2 0.203: v360.07,45.77 360.48,45.77 368.2,53.49 368.2,57.56 379.98,69.34 382.02,69.34 395.02,82.35 C05.V2
  Route15 0.203: v303.58,83.97 308.46,83.97 313.33,79.1 313.74,79.1 314.15,78.69 314.96,78.69 316.99,76.66 316.99,67.72 317.4,67.31 317.4,63.25 v335.28,45.36
  Bottom 0.203: v303.58,83.97 301.14,83.97 297.49,87.63 277.57,87.63 276.76,86.82 272.29,86.82 271.88,87.22 270.66,87.22 269.04,88.85 C15.T2 | v335.28,45.36 335.69,45.77 v360.07,45.77
N$342
  Route15 0.203: C22.V2 178.82,82.75 177.19,82.75 168.66,91.29 168.66,92.91 167.03,94.54 C23.R2
N$343
  Route15 0.203: C22.U2 182.07,86 178,86 173.94,90.07 171.91,90.07 170.28,91.69 C23.S2
N$344
  Route15 0.203: C22.T2 178.82,89.26 176.78,89.26 168.66,97.38 168.66,99.42 167.03,101.04 C23.N2
N$345  (via drill 0.61)
  Top 0.203: v169.88,94.13 169.88,97.79 C23.P2
  Bottom 0.203: v169.88,94.13 170.69,93.32 181.25,93.32 182.07,92.51 C22.S2
N$346
  Route2 0.203: C24.K2 157.68,111.61 160.53,111.61 168.25,119.33 169.88,119.33 178.82,128.27 180.44,128.27 182.07,129.9 C22.C2
N$347  (via drill 0.61)
  Top 0.203: v177.6,115.67 178,116.08 178,125.02 179.22,126.24 C22.D2
  Bottom 0.203: v177.6,115.67 155.25,115.67 154.43,114.86 C24.J2
N$348
  Route2 0.203: C24.M2 157.68,105.1 159.72,105.1 171.09,116.48 173.13,116.48 178.82,122.17 180.85,122.17 182.07,123.39 C22.E2
N$349  (via drill 0.61)
  Top 0.203: v175.16,109.17 178,109.17 178,114.86 178.82,115.67 178.82,120.14 C22.F2
  Bottom 0.203: v175.16,109.17 155.25,109.17 154.43,108.36 C24.L2
N$350
  Route2 0.203: C24.P2 157.68,99.01 161.75,99.01 177.6,114.86 178,114.86 178.82,115.67 180.85,115.67 182.07,116.89 C22.H2
N$351  (via drill 0.61)
  Top 0.203: v175.16,100.63 180.85,106.32 180.85,112.42 179.63,113.64 C22.J2
  Bottom 0.203: v175.16,100.63 174.75,100.23 172.31,100.23 171.5,101.04 169.47,101.04 168.66,100.23 159.72,100.23 159.31,100.63 154.84,100.63 154.43,101.04 C24.N2
N$352  (via drill 0.61)
  Top 0.203: v181.66,94.94 181.25,95.35 181.25,109.17 182.47,110.39 C22.K2
  Bottom 0.203: v181.66,94.94 180.44,93.73 172.72,93.73 171.5,94.94 169.47,94.94 168.25,93.73 158.9,93.73 157.68,92.51 C24.S2
N$353
  Route2 0.203: C24.R2 154.43,95.76 158.9,95.76 159.72,96.57 169.88,96.57 177.6,104.29 177.6,105.51 179.22,107.14 C22.L2
N$354  (via drill 0.61)
  Top 0.203: v170.28,106.32 170.28,110.39 C23.K2
  Bottom 0.203: v170.28,106.32 170.69,105.92 181.25,105.92 182.07,105.1 C22.M2
N$355
  Route15 0.203: C22.N2 179.22,102.26 179.22,103.89 170.69,112.42 169.06,112.42 167.44,114.05 C23.J2
N$356  (via drill 0.61)
  Top 0.203: v169.88,100.23 169.88,104.29 C23.M2
  Bottom 0.203: v169.88,100.23 170.28,99.82 181.25,99.82 182.07,99.01 C22.P2
N$357
  Route15 0.203: C22.R2 178.82,95.76 175.56,95.76 167.44,103.89 167.44,106.73 167.03,107.14 C23.L2
N$358  (via drill 0.61)
  Top 0.203: v210.92,28.3 203.61,35.61 203.61,45.36 206.04,47.8 206.04,57.96 207.67,59.59 D20.C2
  Bottom 0.203: v210.92,28.3 212.55,26.67 228.8,26.67 229.62,25.86 D18.R2
N$359
  Top 0.203: D20.D2 204.83,57.96 206.45,59.59 206.45,60.81 207.26,61.62 212.95,61.62 212.95,53.09 226.77,39.27 234.49,39.27 234.49,23.83 233.68,23.01 D18.S2
N$360
  Route15 0.203: D18.N2 229.62,31.95 227.99,31.95 209.7,50.24 209.7,52.27 208.48,53.49 D20.E2
N$361
  Route15 0.203: D20.F2 205.23,50.24 208.89,50.24 227.58,31.55 228.4,31.55 229.62,30.33 231.65,30.33 232.87,29.11 D18.P2
N$362
  Top 0.203: D18.L2 229.62,38.46 226.37,38.46 218.64,46.18 208.48,46.18 208.48,46.99 D20.H2
N$363
  Top 0.203: D18.M2 232.87,35.2 228.4,35.2 228.4,35.61 218.24,45.77 205.23,45.77 205.23,44.96 D20.J2
N$364
  Bottom 0.203: D20.K2 208.48,41.71 209.7,42.93 228.4,42.93 229.62,44.15 D18.J2
N$365
  Bottom 0.203: D20.L2 205.23,38.46 206.45,39.68 231.65,39.68 232.87,40.89 D18.K2
N$366
  Top 0.203: D20.M2 208.48,35.2 212.95,35.2 212.95,35.61 216.61,39.27 218.64,39.27 218.64,26.67 217.83,25.86 D19.R2
N$367
  Bottom 0.203: D20.N2 204.42,31.14 204.42,26.67 204.01,26.67 203.61,26.26 203.61,23.42 218.64,23.42 219.86,22.2 D19.S2
N$368
  Bottom 0.203: D20.P2 208.48,29.11 209.7,30.33 216.21,30.33 217.02,31.14 D19.N2
N$369
  Bottom 0.203: D20.R2 205.23,25.86 206.45,27.08 208.48,27.08 211.33,29.92 218.64,29.92 219.86,28.7 D19.P2
N$370
  Top 0.203: D20.S2 208.48,22.61 212.95,22.61 212.95,31.55 217.02,35.61 217.02,37.64 D19.L2
N$371
  Route2 0.203: D20.T2 205.23,19.76 205.23,21.39 217.02,33.17 218.24,33.17 219.86,34.8 D19.M2
N$372
  Top 0.203: D20.U2 208.48,16.51 212.14,16.51 212.14,18.14 219.05,25.04 219.05,42.52 217.83,43.74 D19.J2
N$373
  Top 0.203: D20.V2 205.23,13.26 209.7,13.26 219.46,23.01 219.46,39.27 220.68,40.49 D19.K2
N$374  (via drill 0.61)
  Top 0.203: v226.37,80.31 228.8,82.75 228.8,93.32 230.02,94.54 C18.R2
  Bottom 0.203: v226.37,80.31 206.86,80.31 205.23,81.94 C20.V2
N$375
  Route2 0.203: C20.U2 208.48,86 212.55,86 213.77,87.22 217.02,87.22 218.64,85.6 220.27,87.22 226.37,87.22 229.21,90.07 231.24,90.07 232.87,91.69 C18.S2
N$376
  Route2 0.203: C20.T2 205.23,89.26 209.3,89.26 210.11,90.07 216.61,90.07 226.37,99.82 228.4,99.82 229.62,101.04 C18.N2
N$377  (via drill 0.61)
  Top 0.203: v226.77,93.73 230.84,97.79 232.87,97.79 C18.P2
  Bottom 0.203: v226.77,93.73 209.7,93.73 208.48,92.51 C20.S2
N$378  (via drill 0.61)
  Top 0.203: v206.04,104.29 206.04,96.57 205.23,95.76 C20.R2
  Bottom 0.203: v206.04,104.29 206.04,106.73 228.8,106.73 229.62,107.54 C18.L2
N$379  (via drill 0.61)
  Top 0.203: v233.27,100.23 233.27,104.29 C18.M2
  Bottom 0.203: v233.27,100.23 209.7,100.23 208.48,99.01 C20.P2
N$380
  Route2 0.203: C20.N2 205.23,102.26 209.7,102.26 210.51,103.07 217.02,103.07 226.37,112.42 227.99,112.42 229.62,114.05 C18.J2
N$381  (via drill 0.61)
  Top 0.203: v230.02,106.32 232.87,106.32 232.87,110.79 C18.K2
  Bottom 0.203: v230.02,106.32 209.7,106.32 208.48,105.1 C20.M2
N$382  (via drill 0.61)
  Top 0.203: v213.77,127.86 213.77,126.24 218.64,121.36 218.64,113.23 220.27,111.61 C19.K2
  Bottom 0.203: v213.77,127.86 211.73,129.9 208.48,129.9 C20.C2
N$383  (via drill 0.61)
  Top 0.203: v205.64,115.67 206.04,116.08 206.04,125.02 204.83,126.24 C20.D2
  Bottom 0.203: v205.64,115.67 216.21,115.67 217.02,114.86 C19.J2
N$384
  Top 0.203: C19.M2 220.27,105.51 218.64,107.14 218.64,110.39 208.48,120.55 208.48,123.39 C20.E2
N$385
  Route15 0.203: C20.F2 205.23,120.14 207.26,120.14 215.8,111.61 215.8,110.39 217.42,108.76 C19.L2
N$386
  Top 0.203: C19.P2 220.27,99.01 218.64,100.63 218.64,104.7 208.48,114.86 208.48,116.89 C20.H2
N$387
  Top 0.203: C20.J2 205.23,113.64 208.89,113.64 208.89,112.42 217.02,104.29 217.02,102.26 C19.N2
N$388
  Top 0.203: C19.S2 220.27,92.51 219.46,93.32 219.46,97.38 208.08,108.76 208.08,110.39 C20.K2
N$389
  Top 0.203: C20.L2 205.23,107.54 207.26,107.54 217.02,97.79 217.02,95.76 C19.R2
N$390  (via drill 0.61)
  Top 0.203: v171.09,58.78 171.09,25.45 167.44,25.45 D23.R2
  Bottom 0.203: v171.09,58.78 171.5,59.18 181.25,59.18 182.07,60 D22.C2
N$391  (via drill 0.61)
  Top 0.203: v177.19,23.42 178,24.23 178,55.12 179.22,56.34 D22.D2
  Bottom 0.203: v177.19,23.42 171.09,23.42 170.28,22.61 D23.S2
N$392  (via drill 0.61)
  Top 0.203: v168.25,50.24 168.25,33.58 167.03,32.36 D23.N2
  Bottom 0.203: v168.25,50.24 170.69,52.68 178.41,52.68 179.22,53.49 182.07,53.49 D22.E2
N$393  (via drill 0.61)
  Top 0.203: v178.82,27.08 180.85,29.11 180.85,49.02 179.63,50.24 D22.F2
  Bottom 0.203: v178.82,27.08 171.09,27.08 170.28,27.89 D23.P2
N$394
  Route2 0.203: D23.L2 167.44,38.46 170.69,38.46 175.16,42.93 175.97,42.93 178.82,45.77 180.85,45.77 182.07,46.99 D22.H2
N$395
  Route2 0.203: D23.M2 170.28,35.61 170.28,37.24 175.56,42.52 177.19,42.52 178.82,44.15 D22.J2
N$396
  Bottom 0.203: D23.J2 167.44,44.15 169.06,42.52 181.25,42.52 182.07,41.71 D22.K2
N$397
  Bottom 0.203: D23.K2 170.28,40.89 171.91,39.27 178,39.27 178.82,38.46 D22.L2
N$398
  Bottom 0.203: D24.R2 153.62,25.86 153.62,30.33 153.21,30.33 152.81,30.73 152.81,33.58 178,33.58 179.22,34.8 182.07,34.8 D22.M2
N$399
  Bottom 0.203: D24.S2 157.68,22.61 159.31,24.23 180.44,24.23 183.69,27.48 183.69,31.14 179.63,31.14 D22.N2
N$400
  Bottom 0.203: D24.N2 154.43,31.14 155.65,29.92 181.25,29.92 182.07,29.11 D22.P2
N$401
  Bottom 0.203: D24.P2 157.68,28.3 159.31,26.67 178,26.67 178.82,25.86 D22.R2
N$402
  Bottom 0.203: D24.L2 153.62,37.64 153.62,33.98 152.4,33.98 152.4,20.98 181.25,20.98 182.07,21.79 D22.S2
N$403
  Top 0.203: D24.M2 157.68,34.39 158.9,33.17 158.9,12.04 160.12,10.82 180.85,10.82 180.85,17.73 180.03,18.54 D22.T2
N$404
  Top 0.203: D22.U2 182.07,15.29 182.07,5.13 181.66,4.72 155.25,4.72 155.25,42.93 154.43,43.74 D24.J2
N$405
  Top 0.203: D22.V2 178.82,12.45 177.6,11.23 161.75,11.23 161.75,34.8 157.28,39.27 157.28,40.49 D24.K2
N$406  (via drill 0.61)
  Top 0.203: v253.59,151.03 254,151.44 254,174.6 254.41,175.01 254.41,179.48 254,179.88 254,183.54 v254.41,183.95
  Bottom 0.203: v253.59,151.03 254,151.44 257.25,151.44 258.06,152.25 B16.U2 | v254.41,183.95 253.19,183.95 B17.H1
N$407  (via drill 0.61)
  Top 0.203: v251.16,149.4 251.16,192.07 251.97,192.89 251.97,196.14 B17.C1
  Bottom 0.203: v251.16,149.4 254.81,149.4 B16.V2
N$408  (via drill 0.61)
  Top 0.203: v241.4,198.98 241.4,151.03 242.62,149.81 B17.V2
  Bottom 0.203: v241.4,198.98 241.81,198.58 247.9,198.58 248.72,199.39 B17.B1
N$409  (via drill 0.61)
  Top 0.203: v253.59,175.41 253.59,201.83 252.78,202.64 B17.A1
  Bottom 0.203: v253.59,175.41 254,175.82 260.5,175.82 261.31,175.01 B16.L1
N$410
  Route15 0.203: B15.U1 277.57,153.06 277.57,157.12 276.35,158.34 276.35,164.44 251.16,189.64 251.16,191.26 249.53,192.89 B17.D1
N$411  (via drill 0.61)
  Top 0.203: v282.85,224.18 282.85,239.62 282.45,240.03 282.45,248.97 281.23,250.19 A14.J2
  Bottom 0.203: v282.85,224.18 283.26,223.77 284.89,223.77 286.11,222.56 289.76,222.56 A14.U1
N$412
  Top 0.203: A14.K1 290.17,246.94 288.14,244.91 288.14,244.5 A14.L1
  Route2 0.203: A14.M2 284.89,241.66 284.89,242.06 286.92,244.09 A14.L1
N$413  (via drill 0.61)
  Top 0.203: v260.5,139.65 260.5,93.73 259.28,92.51 C16.S2 | v289.76,139.65 290.17,140.06 290.17,150.62 289.36,151.44 289.36,205.49 290.17,206.3 290.17,220.52 288.95,221.74 288.95,236.37 287.73,237.59 A14.N1 286.92,238.81 286.92,241.25 286.11,242.06 286.11,245.31 284.48,246.94 A14.K2
  Route2 0.203: A14.L2 281.63,244.91 281.63,245.31 283.67,247.34 A14.K2
  Bottom 0.203: v260.5,139.65 260.91,140.06 289.36,140.06 v289.76,139.65
N$414  (via drill 0.61)
  Top 0.203: v110.54,230.28 114.2,233.93 114.2,258.32 112.98,259.54 A28A.E1
  Route2 0.203: v17.07,155.91 17.07,157.12 15.85,158.34 15.85,159.16 29.67,172.97 33.33,172.97 34.54,174.19 34.54,177.85 36.17,179.48 v36.17,179.88 | v47.14,179.88 66.24,198.98 66.24,204.67 v91.44,229.87
  Bottom 0.203: v17.07,155.91 12.19,151.03 2.03,151.03 2.03,155.09 B36.T2 | v36.17,179.88 36.58,179.48 46.74,179.48 v47.14,179.88 | v91.44,229.87 91.85,230.28 v110.54,230.28
NEG_CLAMP  (via drill 0.61)
  Top 0.203: v132.89,86.82 132.89,231.5 129.24,231.5 A26.R2 | D23.V2 166.22,13.26 165.41,14.07 165.41,81.13 166.22,81.94 C23.V2
  Bottom 0.203: D18.V2 229.62,13.26 228.8,14.07 219.46,14.07 218.24,12.85 D19.V2 217.02,13.26 216.21,14.07 165.41,14.07 | 151.99,14.07 142.65,14.07 141.83,13.26 D25.V2 | 151.99,14.07 153.21,12.85 D24.V2 | 165.41,14.07 166.22,13.26 D23.V2 | 165.41,14.07 151.99,14.07 | C18.V2 229.62,82.75 228.4,83.97 219.46,83.97 218.24,82.75 C19.V2 217.02,83.16 216.21,83.97 168.66,83.97 167.44,82.75 C23.V2 166.22,81.94 165.41,81.13 151.99,81.13 | 151.99,81.13 142.65,81.13 141.83,81.94 C25.V2 140.61,82.75 136.96,82.75 v132.89,86.82 | 151.99,81.13 153.21,82.35 C24.V2
NO_SHIFT  (via drill 0.61)
  Top 0.203: v383.64,204.27 384.45,205.08 384.45,238 390.14,243.69 390.14,257.91 391.77,259.54 AB06.AE1
  Route2 0.203: v361.29,181.91 v383.64,204.27
  Bottom 0.203: 416.15,261.57 406.81,261.57 405.59,260.35 AB05.AE1 404.37,260.76 403.56,261.57 390.55,261.57 | 416.15,261.57 416.97,260.76 AB04.AE1 | 428.75,261.57 429.56,260.76 AB03.AE1 | 416.15,261.57 428.75,261.57 | 428.75,261.57 441.35,261.57 442.16,260.76 AB02.AE1 | A09.E1 354.79,260.35 355.19,260.76 358.85,260.76 359.66,261.57 377.95,261.57 378.76,260.76 AB07.AE1 379.98,260.76 380.8,261.57 390.55,261.57 | v361.29,181.91 360.88,182.32 340.16,182.32 338.94,181.1 B10.J1 | 390.55,261.57 391.36,260.76 AB06.AE1
OP1  (via drill 0.61)
  Top 0.203: v343,97.38 343,40.08 344.22,38.86 D09.L2 | v365.76,96.98 365.35,97.38 365.35,113.64 369.42,117.7 369.42,120.14 C07.F2 | 321.06,255.47 321.06,258.32 322.27,259.54 A11.E2 | 321.06,255.47 321.06,248.97 321.87,248.16 A11.K2 | A09.D1 351.54,263.6 353.57,265.63 353.57,266.04 A09.C1 | 324.31,255.47 324.31,255.88 325.12,256.69 A11.F1 325.12,257.91 324.31,258.72 324.31,268.48 325.12,269.29 A11.B1 | 324.31,255.47 324.31,245.31 324.71,244.91 A11.L1 | 324.31,255.47 321.06,255.47 | A12.H1 315.37,253.44 314.55,252.63 314.55,224.18 315.77,222.96 A12.U1 316.18,221.74 316.99,220.93 316.99,205.49 v316.59,205.08 | v304.8,205.08 304.39,204.67 304.39,185.57 303.58,184.76 B13.H1
  Route15 0.203: C07.F2 369.42,120.95 365.76,120.95 355.19,131.52 350.72,131.52 343.81,138.43 343.81,139.24 335.69,147.37 335.69,148.18 321.87,162 321.87,163.63 311.3,174.19 311.3,177.85 306.83,182.32 305.61,182.32 303.99,183.95 B13.H1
